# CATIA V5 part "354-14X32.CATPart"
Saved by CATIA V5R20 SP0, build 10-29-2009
Part number: 354-14X32
Definition: NONE
Nomenclature: 354-14X32
Source: Unknown
Description: 354-14X32
Bounding box of the stored display mesh (mm): x -16 to 16, y -12 to 12, z -12 to 12
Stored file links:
  C:\Users\Utente\Desktop\IO LAVORO\3D X SITO CF\X SITO\PLASTICA\354\354-14X32.CATPart
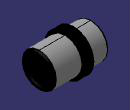
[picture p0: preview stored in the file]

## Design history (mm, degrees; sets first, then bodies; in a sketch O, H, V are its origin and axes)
Body1 "354-14X32" (main body)
  Solid1: solid without history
